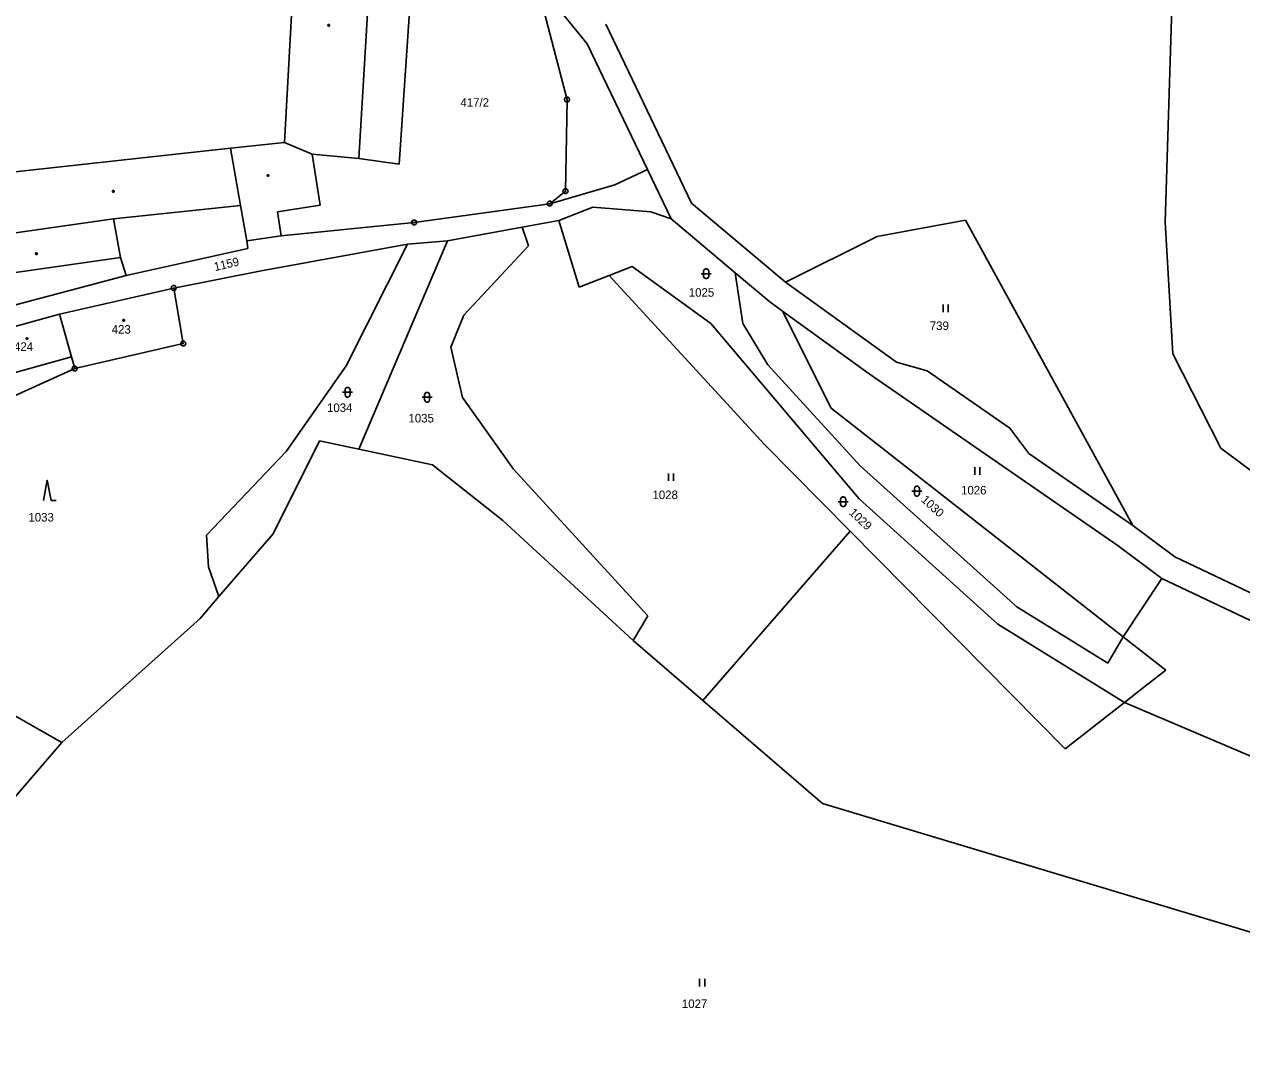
# Model space of a CAD drawing. Extents: x -812394 to -807601, y -1013098 to -1009266.
# Drawn here: x -810997.6 to -810755.5, y -1011891.2 to -1011688.8 of the extents above; entities that cross this region are included whole.
import ezdxf

# ---------------------------------------------------------------- set-up
doc = ezdxf.new("R2010")
doc.units = 0
for name, color, linetype in [('KN_HRANICE', 7, 'Continuous'), ('KN_KULTURY', 7, 'Continuous'), ('KN_MEZNIKY', 7, 'Continuous'), ('KN_PARCELY', 7, 'Continuous'), ('KN_SLUCKY', 7, 'Continuous')]:
    doc.layers.add(name, color=color, linetype=linetype)

# ---------------------------------------------------------------- blocks, each defined once
blk = doc.blocks.new('306')
for p, q in [((-0.5, 1.5), (-0.5, 0)), ((0.5, 0), (0.5, 1.5))]:
    blk.add_line(p, q)
blk = doc.blocks.new('308')
blk.add_lwpolyline([(-0.75, 0), (0, 4), (0.75, 0), (1.75, 0)])
blk = doc.blocks.new('316')
for points in [[(-1, 1), (0.27, 1), (1, 1)], [(-0.5, 1.5), (-0.4, 1.79), (-0.15, 1.97), (0.16, 1.97), (0.41, 1.79), (0.51, 1.5), (0.51, 0.5), (0.41, 0.21), (0.16, 0.03), (-0.15, 0.03), (-0.4, 0.21), (-0.5, 0.5), (-0.5, 1.5)]]:
    blk.add_lwpolyline(points)
blk = doc.blocks.new('NAHRADNI_SYMBOL')
blk.add_lwpolyline([(0.09, 0.15), (0.18, 0), (0.09, -0.15), (-0.09, -0.15), (-0.18, 0), (-0.09, 0.15), (0.09, 0.15)])
blk = doc.blocks.new('402')
blk.add_lwpolyline([(0.09, 0.15), (0.18, 0), (0.09, -0.15), (-0.09, -0.15), (-0.18, 0), (-0.09, 0.15), (0.09, 0.15)])
blk = doc.blocks.new('105')
blk.add_line((-0.12, 0), (0.12, 0))
blk.add_lwpolyline([(0.15, 0.48), (0.4, 0.3), (0.5, 0.01), (0.4, -0.28), (0.15, -0.46), (-0.16, -0.46), (-0.41, -0.28), (-0.51, 0.01), (-0.41, 0.3), (-0.16, 0.48), (0.15, 0.48)])

msp = doc.modelspace()

# ---------------------------------------------------------------- linework, layer by layer
at = {"layer": 'KN_HRANICE'}
for p, q in [((-810910.24, -1011662.33), (-810885.61, -1011692.65)), ((-810923.04, -1011716.62), (-810919.67, -1011667.84)), ((-810770.67, -1011728.15), (-810769.26, -1011682.72)), ((-810889.63, -1011703.76), (-810894.15, -1011686.31)), ((-810875.9, -1011701.34), (-810881.94, -1011688.74)), ((-810885.61, -1011692.65), (-810873.63, -1011717.68)), ((-810864.89, -1011724.35), (-810875.9, -1011701.34)), ((-810889.92, -1011721.98), (-810889.63, -1011703.76)), ((-810940.3, -1011714.57), (-810931.06, -1011715.46)), ((-810940.3, -1011714.57), (-810938.7, -1011724.76)), ((-810931.06, -1011715.46), (-810923.04, -1011716.62)), ((-810880.1, -1011720.69), (-810873.63, -1011717.68)), ((-810873.63, -1011717.68), (-810868.94, -1011727.48)), ((-810893.06, -1011724.45), (-810880.1, -1011720.69)), ((-810893.06, -1011724.45), (-810889.92, -1011721.98)), ((-810938.7, -1011724.76), (-810947.2, -1011726.09)), ((-810947.2, -1011726.09), (-810946.5, -1011730.84)), ((-810920.02, -1011728.18), (-810893.06, -1011724.45)), ((-810891.27, -1011727.77), (-810884.49, -1011725.13)), ((-810884.49, -1011725.13), (-810872.93, -1011726.05)), ((-810872.93, -1011726.05), (-810868.94, -1011727.48)), ((-810846.21, -1011740.05), (-810864.89, -1011724.35)), ((-810946.5, -1011730.84), (-810920.02, -1011728.18)), ((-810898.52, -1011729.11), (-810891.27, -1011727.77)), ((-810891.27, -1011727.77), (-810887.22, -1011741.06)), ((-810868.94, -1011727.48), (-810856.2, -1011738.19)), ((-810827.94, -1011730.95), (-810810.37, -1011727.72)), ((-810810.37, -1011727.72), (-810777.11, -1011788.45)), ((-810769.15, -1011754.35), (-810770.67, -1011728.15)), ((-810953.32, -1011731.84), (-810946.5, -1011730.84)), ((-810913.39, -1011731.87), (-810898.52, -1011729.11)), ((-810897.26, -1011732.84), (-810898.52, -1011729.11)), ((-810846.21, -1011740.05), (-810827.94, -1011730.95)), ((-810977.33, -1011738.74), (-810953.08, -1011733.36)), ((-810953.08, -1011733.36), (-810953.32, -1011731.84)), ((-810950.77, -1011737.88), (-810921.33, -1011732.51)), ((-810931, -1011773.27), (-810913.39, -1011731.87)), ((-810921.33, -1011732.51), (-810913.39, -1011731.87)), ((-810910.16, -1011746.66), (-810897.26, -1011732.84)), ((-810967.84, -1011741.23), (-810950.77, -1011737.88)), ((-810856.2, -1011738.19), (-810854.67, -1011748.28)), ((-810856.2, -1011738.19), (-810849.29, -1011744)), ((-811010.19, -1011747.48), (-810977.33, -1011738.74)), ((-810887.22, -1011741.06), (-810881.22, -1011738.72)), ((-810881.22, -1011738.72), (-810850.37, -1011772.33)), ((-810824.08, -1011755.96), (-810846.21, -1011740.05)), ((-810967.84, -1011741.23), (-810990.56, -1011746.41)), ((-810849.29, -1011744), (-810846.78, -1011745.82)), ((-810990.56, -1011746.41), (-811006.21, -1011750.72)), ((-810990.56, -1011746.41), (-810988.18, -1011754.95)), ((-810912.73, -1011753.01), (-810910.16, -1011746.66)), ((-810846.78, -1011745.82), (-810829.53, -1011758.27)), ((-810837.1, -1011765.11), (-810846.78, -1011745.82)), ((-810910.4, -1011763.04), (-810912.73, -1011753.01)), ((-810988.18, -1011754.95), (-810987.54, -1011757.25)), ((-810759.6, -1011773.11), (-810769.15, -1011754.35)), ((-811005.63, -1011765.4), (-810987.54, -1011757.25)), ((-810818.01, -1011757.72), (-810824.08, -1011755.96)), ((-810801.56, -1011769.1), (-810818.01, -1011757.72)), ((-810829.53, -1011758.27), (-810780.03, -1011792.51)), ((-810900.26, -1011777.28), (-810910.4, -1011763.04)), ((-810779.05, -1011810.59), (-810837.1, -1011765.11)), ((-810797.76, -1011774.16), (-810801.56, -1011769.1)), ((-810948.07, -1011790.14), (-810938.83, -1011771.61)), ((-810938.83, -1011771.61), (-810931, -1011773.27)), ((-810850.37, -1011772.33), (-810833.33, -1011789.58)), ((-810931, -1011773.27), (-810916.4, -1011776.38)), ((-810777.11, -1011788.45), (-810797.76, -1011774.16)), ((-810734.95, -1011791.55), (-810759.6, -1011773.11)), ((-810916.4, -1011776.38), (-810902.39, -1011787.45)), ((-810873.56, -1011806.45), (-810900.26, -1011777.28)), ((-810902.39, -1011787.45), (-810876.5, -1011811.36)), ((-810768.74, -1011794.72), (-810777.11, -1011788.45)), ((-810960.96, -1011796.71), (-810961.35, -1011790.39)), ((-810958.86, -1011802.61), (-810948.07, -1011790.14)), ((-810833.33, -1011789.58), (-810862.64, -1011823.29)), ((-810833.33, -1011789.58), (-810790.53, -1011832.9)), ((-810780.03, -1011792.51), (-810771.3, -1011799.04)), ((-810990.1, -1011831.63), (-811055.79, -1011794.38)), ((-810738.04, -1011809.35), (-810768.74, -1011794.72)), ((-810958.86, -1011802.61), (-810960.96, -1011796.71)), ((-810779.05, -1011810.59), (-810771.3, -1011799.04)), ((-810771.3, -1011799.04), (-810722.88, -1011822.01)), ((-810962.6, -1011806.94), (-810958.86, -1011802.61)), ((-810990.1, -1011831.63), (-810962.6, -1011806.94)), ((-810876.5, -1011811.36), (-810873.56, -1011806.45)), ((-810779.05, -1011810.59), (-810782.06, -1011815.84)), ((-810770.57, -1011817.24), (-810779.05, -1011810.59)), ((-810876.5, -1011811.36), (-810862.64, -1011823.29)), ((-810774.63, -1011820.43), (-810770.57, -1011817.24)), ((-810774.63, -1011820.43), (-810778.75, -1011823.66)), ((-810862.64, -1011823.29), (-810838.82, -1011843.8)), ((-810790.53, -1011832.9), (-810778.75, -1011823.66)), ((-810735.32, -1011842.24), (-810778.75, -1011823.66)), ((-811014.6, -1011860.1), (-810990.1, -1011831.63)), ((-810838.82, -1011843.8), (-810681.36, -1011891.15))]:
    msp.add_line(p, q, dxfattribs=at)
for points in [[(-810961.35, -1011790.39), (-810945.5, -1011773.77), (-810933.55, -1011756.72), (-810921.33, -1011732.51)], [(-810778.75, -1011823.66), (-810803.98, -1011808.11), (-810831.53, -1011783.14), (-810861.05, -1011748.31), (-810876.68, -1011736.95), (-810881.22, -1011738.72)], [(-810987.54, -1011757.25), (-810965.94, -1011752.29), (-810967.84, -1011741.23)], [(-810854.67, -1011748.28), (-810849.68, -1011756.49), (-810831.3, -1011776.59), (-810800.17, -1011804.67), (-810782.06, -1011815.84)]]:
    msp.add_lwpolyline(points, dxfattribs=at)
at = {"layer": 'KN_SLUCKY'}
for p, q in [((-810943.04, -1011661.57), (-810945.82, -1011712.25)), ((-810931.06, -1011715.46), (-810927.88, -1011662.52)), ((-810956.56, -1011713.43), (-811006.65, -1011718.94)), ((-810945.82, -1011712.25), (-810956.56, -1011713.43)), ((-810954.56, -1011724.79), (-810956.56, -1011713.43)), ((-810945.82, -1011712.25), (-810940.3, -1011714.57)), ((-810979.82, -1011727.46), (-810954.56, -1011724.79)), ((-810953.32, -1011731.84), (-810954.56, -1011724.79)), ((-811012.33, -1011732.15), (-810979.82, -1011727.46)), ((-810979.82, -1011727.46), (-810978.44, -1011735.16)), ((-810978.44, -1011735.16), (-811011.17, -1011739.82)), ((-810978.44, -1011735.16), (-810977.33, -1011738.74))]:
    msp.add_line(p, q, dxfattribs=at)
msp.add_lwpolyline([(-811006.21, -1011750.72), (-811003.67, -1011759.26), (-810988.18, -1011754.95)], dxfattribs=at)

# ---------------------------------------------------------------- block references
at = {"layer": 'KN_KULTURY'}
for name, p in [('402', (-810937.02, -1011688.96)), ('402', (-810949.11, -1011718.86)), ('402', (-810979.87, -1011721.99)), ('402', (-810995.15, -1011734.38)), ('316', (-810861.96, -1011739.38)), ('306', (-810814.34, -1011746.03)), ('NAHRADNI_SYMBOL', (-810977.8, -1011747.67)), ('402', (-810997.02, -1011751.26)), ('316', (-810933.27, -1011762.96)), ('316', (-810917.47, -1011763.95)), ('306', (-810808.04, -1011778.37)), ('308', (-810993, -1011783.47)), ('306', (-810868.96, -1011779.6)), ('316', (-810820.04, -1011782.64)), ('316', (-810834.72, -1011784.74)), ('306', (-810862.75, -1011880.17))]:
    msp.add_blockref(name, p, dxfattribs=at)
at = {"layer": 'KN_MEZNIKY'}
for p in [(-810889.63, -1011703.76), (-810889.92, -1011721.98), (-810893.06, -1011724.45), (-810920.02, -1011728.18), (-810967.84, -1011741.23), (-810965.94, -1011752.29), (-810987.54, -1011757.25)]:
    msp.add_blockref('105', p, dxfattribs=at)

# ---------------------------------------------------------------- texts
at = {"layer": 'KN_PARCELY'}
for s, p in [('417/2', (-810910.83, -1011705.17)), ('1025', (-810865.42, -1011742.96)), ('739', (-810817.48, -1011749.58)), ('423', (-810980.18, -1011750.3)), ('424', (-810999.61, -1011753.73)), ('1034', (-810937.36, -1011765.89)), ('1035', (-810921.16, -1011767.97)), ('1028', (-810872.63, -1011783.22)), ('1026', (-810811.26, -1011782.29)), ('1033', (-810996.75, -1011787.68)), ('1027', (-810866.78, -1011884.46))]:
    msp.add_text(s, height=1.7, dxfattribs=at).set_placement(p)
for s, rotation, p in [('1159', 13.293, (-810959.63, -1011737.88)), ('1030', 317.018, (-810819.33, -1011783.52)), ('1029', 316.674, (-810833.67, -1011786.08))]:
    msp.add_text(s, height=1.7, rotation=rotation, dxfattribs=at).set_placement(p)

doc.saveas('drawing.dxf')
